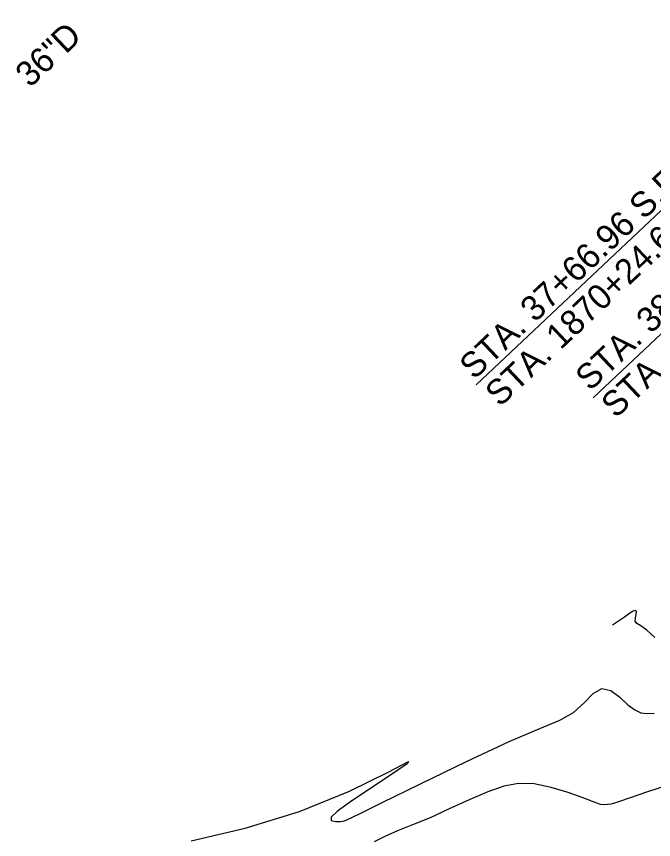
# Model space of a CAD drawing. Extents: x -291892836 to 2945206, y -477993085 to 1832792.
# Drawn here: x 1848544 to 1849500, y 542208 to 543443 of the extents above; entities that cross this region are included whole.
import ezdxf

# ---------------------------------------------------------------- set-up
doc = ezdxf.new("R2010")
doc.units = 0
doc.layers.add('DT_X_Contour_Minor', color=7, linetype='Continuous')
doc.layers.add('Level 40', color=7, linetype='Continuous')

msp = doc.modelspace()

# ---------------------------------------------------------------- linework, layer by layer
at = {"layer": 'DT_X_Contour_Minor'}
for points in [[(1849501.3, 542511.4), (1849489.3, 542522.2), (1849480.3, 542528.7), (1849474.7, 542532.3), (1849472.2, 542535.7), (1849472.3, 542540.7), (1849473.4, 542546.1), (1849473.9, 542550.3), (1849472.3, 542551.9), (1849468.8, 542550.9), (1849464, 542547.7), (1849456.2, 542541.8), (1849438.2, 542529.8)], [(1848806.3, 542206.2), (1848887, 542225.2), (1848968.8, 542250.3), (1849043.6, 542281.1), (1849101.5, 542309.5), (1849132.3, 542325.4), (1849130.1, 542321.9), (1849105.3, 542304.9), (1849072.8, 542283.4), (1849045.2, 542264.9), (1849025.8, 542251), (1849016, 542241.7), (1849016.1, 542236.9), (1849022.4, 542235.3), (1849030, 542235.6), (1849035.4, 542236.5), (1849038.6, 542237.6), (1849059.6, 542247.4), (1849092.8, 542263.7), (1849150, 542292), (1849218.9, 542325.6), (1849282.9, 542355.4), (1849328.9, 542374.8), (1849359.2, 542387.2), (1849379.6, 542398.8), (1849395.4, 542413.5), (1849408.9, 542427.5), (1849421.9, 542434.9), (1849435.4, 542431.8), (1849448.8, 542421.9), (1849461, 542410.6), (1849471.3, 542402.7), (1849480.6, 542398.4), (1849489.9, 542397.2), (1849500.6, 542398)], [(1849520.1, 542289.5), (1849490.5, 542279.7), (1849449.9, 542265.8), (1849441, 542262.9), (1849435.5, 542261.5), (1849430.5, 542260.7), (1849425.3, 542260.5), (1849420.1, 542261.1), (1849414.6, 542262.9), (1849392.5, 542271.6), (1849371.5, 542279.1), (1849346, 542286.6), (1849320.3, 542291.7), (1849297.1, 542292.3), (1849274.9, 542288.3), (1849250.8, 542279.9), (1849223, 542267.9), (1849193.3, 542254.2), (1849164.4, 542241), (1849138.3, 542230.2), (1849115.7, 542221.2), (1849096.5, 542213), (1849080.8, 542204.9)]]:
    msp.add_lwpolyline(points, dxfattribs=at)
at = {"layer": 'Level 40'}
for p, q in [((1849233.6, 542890.3), (1849832.5, 543455.6)), ((1849408.8, 542871), (1850007.6, 543436.2))]:
    msp.add_line(p, q, dxfattribs=at)

# ---------------------------------------------------------------- texts
for s, p in [('36"D', (1848564.6, 543335.2)), ('STA. 37+66.96 S.R. 424 =', (1849230.5, 542897)), ('STA. 1870+24.65 RAMP "B"', (1849269.1, 542856.1)), ('STA. 38+07.96 S.R. 424 =', (1849404.3, 542879.9)), ('STA. 1901+67.03 RAMP "A"', (1849442.9, 542839))]:
    msp.add_text(s, height=37.5, rotation=43.3446, dxfattribs=at).set_placement(p)

doc.saveas('drawing.dxf')
